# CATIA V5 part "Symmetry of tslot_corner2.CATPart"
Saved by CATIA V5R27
Part number: Symmetry of tslot_corner2
Bounding box of the stored display mesh (mm): x -19.05 to 19.05, y -19.05 to 19.05, z -1374.764 to -1219.2
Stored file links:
  \\triton.meca.polymtl.ca\usagers\zaoue\profiles\Desktop\varm_ass\structure prismatique\Symmetry of tslot_corner2.CATPart
  \\triton.meca.polymtl.ca\usagers\zaoue\profiles\Desktop\varm_ass\structure prismatique\tslot_corner2.CATPart
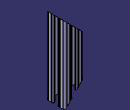
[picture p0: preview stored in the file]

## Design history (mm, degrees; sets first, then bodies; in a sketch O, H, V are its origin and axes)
Body1 (main body)
Body2 "Boss-Extrude1"
  Solid1: linked copy from another document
